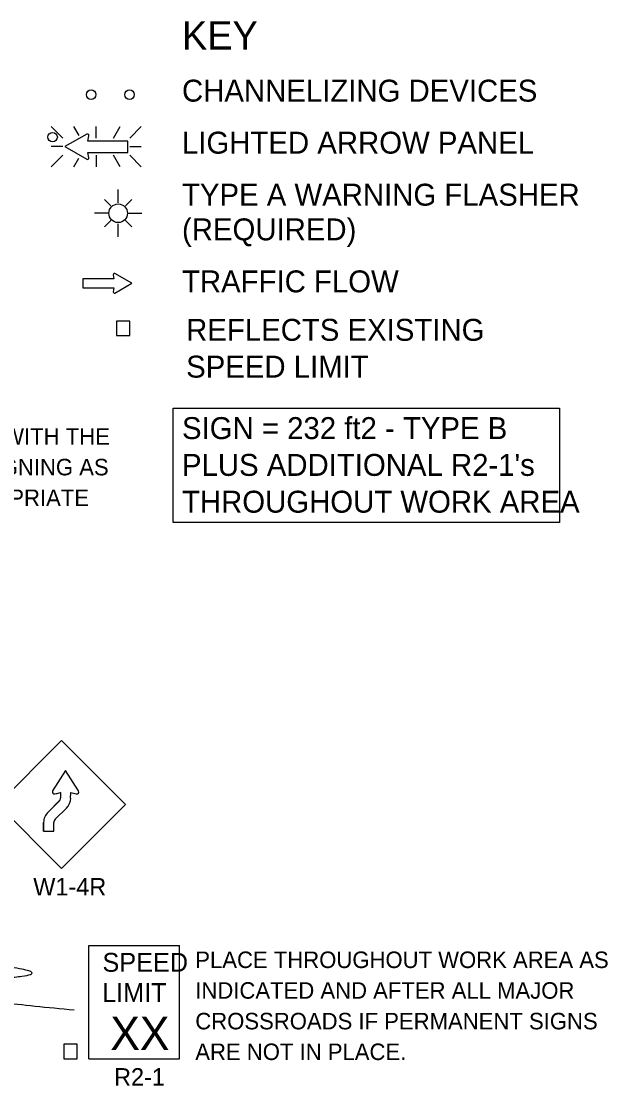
# Model space of a CAD drawing. Extents: x 16731 to 18475, y 7218 to 8213.
# Drawn here: x 17176 to 17424.6, y 7756.4 to 8207.6 of the extents above; entities that cross this region are included whole.
import ezdxf

# ---------------------------------------------------------------- set-up
doc = ezdxf.new("R2010")
doc.units = 0
for name, color, linetype in [('MT_SCRATCH_LEVEL_E', 7, 'Continuous'), ('TRAFFIC_SIGNS_PR', 7, 'Continuous'), ('TYPICAL_TEXT_DIMEN_EX', 7, 'Continuous')]:
    doc.layers.add(name, color=color, linetype=linetype)

msp = doc.modelspace()

# ---------------------------------------------------------------- linework, layer by layer
at = {"layer": 'MT_SCRATCH_LEVEL_E'}
for p, q in [((17214.96, 8100.22), (17215.27, 8098.44)), ((17214.96, 8100.22), (17215.27, 8098.44)), ((17222.88, 8096.59), (17215.64, 8100.7)), ((17222.88, 8096.59), (17215.64, 8100.7)), ((17215.27, 8098.44), (17202.01, 8098.44)), ((17202.01, 8098.44), (17202.01, 8094.7)), ((17215.27, 8098.44), (17202.01, 8098.44)), ((17202.01, 8098.44), (17202.01, 8094.7)), ((17202.01, 8094.7), (17215.27, 8094.7)), ((17202.01, 8094.7), (17215.27, 8094.7)), ((17215.27, 8094.7), (17214.96, 8092.92)), ((17215.27, 8094.7), (17214.96, 8092.92)), ((17215.64, 8092.44), (17222.88, 8096.59)), ((17215.64, 8092.44), (17222.88, 8096.59))]:
    msp.add_line(p, q, dxfattribs=at)
for centre, start, end in [((17215.42, 8100.29), 60.4248, 189.9638), ((17215.42, 8100.29), 60.4248, 189.9638), ((17215.42, 8092.85), 170.0362, 299.7731), ((17215.42, 8092.85), 170.0362, 299.7731)]:
    msp.add_arc(centre, 0.463, start, end, dxfattribs=at)
at = {"layer": 'TRAFFIC_SIGNS_PR'}
for p, q in [((17188.69, 8162.97), (17193.63, 8158.04)), ((17200.45, 8159.15), (17198.25, 8162.97)), ((17207.77, 8158.04), (17207.77, 8162.97)), ((17215.01, 8158.04), (17217.86, 8162.97)), ((17221.92, 8158.04), (17226.86, 8162.98)), ((17193.63, 8154.48), (17188.69, 8154.48)), ((17221.92, 8154.48), (17226.86, 8154.48)), ((17188.69, 8146), (17193.63, 8150.93)), ((17198.2, 8145.99), (17200.32, 8149.65)), ((17207.77, 8150.93), (17207.77, 8145.99)), ((17217.9, 8145.99), (17215.05, 8150.93)), ((17221.92, 8150.93), (17226.86, 8145.99)), ((17217.03, 8130.69), (17217.03, 8136.31)), ((17213.89, 8129.39), (17211.26, 8132.02)), ((17220.17, 8129.39), (17222.8, 8132.02)), ((17213.09, 8126.25), (17207.06, 8126.25)), ((17220.97, 8126.25), (17227.06, 8126.25)), ((17213.89, 8123.12), (17211.26, 8120.48)), ((17217.03, 8116.31), (17217.03, 8121.82)), ((17220.17, 8123.12), (17222.8, 8120.49)), ((17192.97, 7902.81), (17165.82, 7875.65)), ((17220.12, 7875.65), (17192.97, 7902.81)), ((17165.82, 7875.65), (17192.97, 7848.5)), ((17187.31, 7872.4), (17192.03, 7877.12)), ((17192.03, 7877.11), (17187.31, 7872.4)), ((17190.36, 7869.35), (17195.08, 7874.06)), ((17190.37, 7869.35), (17195.08, 7874.06)), ((17192.97, 7848.5), (17220.12, 7875.65)), ((17185.45, 7864.28), (17185.45, 7867.98)), ((17185.45, 7864.28), (17189.76, 7864.28)), ((17189.76, 7864.28), (17189.76, 7867.98)), ((17204.62, 7815.87), (17243.02, 7815.87)), ((17204.62, 7767.87), (17204.62, 7815.87)), ((17243.02, 7767.87), (17243.02, 7815.87)), ((17204.62, 7767.87), (17243.02, 7767.87))]:
    msp.add_line(p, q, dxfattribs=at)
for points in [[(17203.7, 8159.76), (17194.41, 8154.48), (17203.7, 8149.16)], [(17204.58, 8149.79), (17204.18, 8152.06), (17221.19, 8152.06), (17221.19, 8156.86), (17204.18, 8156.86), (17204.58, 8159.14)], [(17200.23, 7881.39), (17194.75, 7890), (17189.27, 7881.39)], [(17200.23, 7881.39), (17194.75, 7890), (17189.27, 7881.39)], [(17190.23, 7880.09), (17192.59, 7880.74), (17192.59, 7878.45)], [(17190.23, 7880.09), (17191.06, 7880.32), (17192.59, 7880.74), (17192.59, 7878.45)], [(17196.9, 7878.37), (17196.91, 7880.74), (17199.27, 7880.09)], [(17185.45, 7867.98), (17185.45, 7864.28), (17189.76, 7864.28), (17189.76, 7867.98)]]:
    msp.add_lwpolyline(points, dxfattribs=at)
for points in [[(17216.38, 8074.39), (17221.98, 8074.39), (17221.98, 8080.56), (17216.38, 8080.56)], [(17194.01, 7767.87), (17199.6, 7767.87), (17199.6, 7774.04), (17194.01, 7774.04)]]:
    msp.add_lwpolyline(points, close=True, dxfattribs=at)
for centre, radius in [((17205.56, 8176.52), 2), ((17221.86, 8176.52), 2), ((17189.26, 8158.52), 2), ((17217.03, 8126.25), 3.94)]:
    msp.add_circle(centre, radius, dxfattribs=at)
for centre, radius, start, end in [((17203.99, 8159.24), 0.598, 350.7308, 118.8916), ((17203.99, 8149.69), 0.597, 241.4833, 9.9593), ((17190, 7880.93), 0.866, 147.5288, 285.3852), ((17190, 7880.93), 0.864, 147.5204, 285.3986), ((17190.74, 7878.44), 1.85, 314.2123, 0.1238), ((17190.74, 7878.44), 1.85, 314.2125, 0), ((17190.74, 7878.44), 6.17, 314.2125, 359.3819), ((17190.74, 7878.44), 6.17, 314.7687, 359.3755), ((17199.5, 7880.93), 0.866, 254.6799, 32.2804), ((17191.61, 7867.98), 6.17, 134.2125, 180), ((17191.61, 7867.98), 6.17, 134.2125, 180), ((17191.61, 7867.98), 6.17, 134.2117, 180), ((17191.61, 7867.98), 1.85, 132.372, 180), ((17191.61, 7867.98), 1.85, 134.2125, 180)]:
    msp.add_arc(centre, radius, start, end, dxfattribs=at)
msp.add_open_spline([(17198.45, 7788.41), (17090.03, 7798.74), (17218.74, 7803.94), (17125.21, 7811.03)], degree=2, dxfattribs=at)
at = {"layer": 'TYPICAL_TEXT_DIMEN_EX'}
msp.add_lwpolyline([(17240.33, 8043.7), (17404.09, 8043.7), (17404.09, 7995.14), (17240.33, 7995.14)], close=True, dxfattribs=at)

# ---------------------------------------------------------------- texts
at = {"layer": 'TRAFFIC_SIGNS_PR'}
for s, height, p in [('PLACE THIS SIGN ALONG WITH THE', 7, (17050.22, 8028.15)), ('ADVANCE WORK ZONE SIGNING AS', 7, (17050.22, 8015.15)), ('DEPICTED ON THE APPROPRIATE', 7, (17050.22, 8002.15)), ('W1-4R', 7.44, (17181.04, 7837.06)), ('SPEED', 8, (17210.39, 7804.73)), ('PLACE THROUGHOUT WORK AREA AS', 7, (17249.73, 7806.31)), ('LIMIT', 8, (17210.23, 7791.93)), ('INDICATED AND AFTER ALL MAJOR', 7, (17249.73, 7793.31)), ('XX', 14.031, (17213.73, 7771.63)), ('CROSSROADS IF PERMANENT SIGNS', 7, (17249.73, 7780.31)), ('ARE NOT IN PLACE.', 7, (17249.73, 7767.31)), ('R2-1', 7.44, (17215.3, 7756.43))]:
    msp.add_text(s, height=height, dxfattribs=at).set_placement(p)
at = {"layer": 'TYPICAL_TEXT_DIMEN_EX'}
for s, height, p in [('KEY', 12, (17244.1, 8195.62)), ('CHANNELIZING DEVICES', 9.3, (17244.1, 8173.57)), ('LIGHTED ARROW PANEL', 9.3, (17244.1, 8151.52)), ('TYPE A WARNING FLASHER', 9.3, (17244.1, 8129.47)), ('(REQUIRED)', 9.3, (17244.1, 8114.77)), ('TRAFFIC FLOW', 9.3, (17244.1, 8092.72)), ('REFLECTS EXISTING', 9.3, (17245.86, 8072.18)), ('SPEED LIMIT', 9.3, (17245.86, 8056.58)), ('SIGN = 232 ft2 - TYPE B', 9.3, (17244.1, 8030.53)), ("PLUS ADDITIONAL R2-1's", 9.3, (17244.1, 8014.93)), ('THROUGHOUT WORK AREA', 9.3, (17244.1, 7999.33))]:
    msp.add_text(s, height=height, dxfattribs=at).set_placement(p)

doc.saveas('drawing.dxf')
